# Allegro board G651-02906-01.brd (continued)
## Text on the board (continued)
User.45: FIGURE | SIZE | 0.8 | 0.1 | 0.15 | 0.2 | DRILL CHART: TOP to BOTTOM | ALL UNITS ARE IN MILLIMETERS | DRILL CHART: TOP to L2 | DRILL CHART: L3 to BOTTOM | DRILL CHART: L2 to L3 | TOLERANCE | +0.05/-0.05 | +0.0/-0.0 | PLATED | NON-PLATED | QTY | 2 | 234 | 252 | 231 | TP15 | TP16 | R8 | DS1 | L4 | TP1 | TP3 | L3 | Y2 | C8 | TP4 | TP9 | TP2 | TP10 | TP8 | R2 | R1 | R5 | R6 | R3 | R4 | R20 | R18 | R13 | R7 | C16 | C1 | C2 | R9 | TP18 | TP17 | C10 | C9 | D1 | D2 | L1 | C7 | C19 | L2 | C18 | C17 | R11 | C15 | C13 | C22 | C20 | C23 | C21 | C24 | R19 | C12 | R12 | R17 | Q2 | Q1 | C6 | C5 | DS2 | PCB edge | FAB NOTES: UNLESS OTHERWISE SPECIFIED | 1. FABRICATION STANDARDS | A) FABRICATE BOARDS IN ACCORDANCE WITH IPC-A-600 AND IPC-6012, CLASS 2. FINISHED BOARDS MUST MEET QUALITY CONFORMANCE TESTING AND INSPECTION AS SPECIFIED. | B) THE CONTROLLING UNIT OF MEASURE FOR THIS DRAWING AND THE SUPPLIED DATA IS METRICS OF INTERNATIONAL SYSTEM OF UNITS. DIMENSIONS THAT ARE SHOWN IN INCHES | ARE FOR REFERENCE ONLY. | C) THIS BOARD HAS CONTROLLED IMPEDANCE REQUIREMENTS. SEE IMPEDANCE CHARTS ON THIS SHEET. UNLESS OTHERWISE SPECIFIED, IMPEDANCE TOLERANCE IS +/- 10%. | D) BOW AND TWIST SHALL NOT EXCEED 0.75% MEASURED IN ACCORDANCE WITH IPC-TM-650. | E) REFER FAB MCO DRAWING PDF (*XXX-XXXXX-XX_MCO.PDF) FOR DIMENSIONS AND TOLERANCE DETAILS. MCO DRAWING TAKES FIRST PRIORITY AND DIMENSIONS NOT SPECIFIED | IN THE DRAWING SHALL BE CONTROLLED BY GERBER/ODB DATA. | 2. MATERIAL: | Optional 2.1 GLASS EPOXY, NATURAL COLOR, LAMINATED POLYCLAD EM390 OR EQUIVALENT. Tg OF 170C MINIMUM, CTE</= 3% PER | IPC-4101/4106 LATEST REVISION, MATERIAL TO BE HALOGEN FREE, MATERIAL MUST MEET UL 796/V-0 FLAMMABILITY RATING. | THE FINAL THICKNESS MEASURED OVER PLATING TO BE xxx mm, +/- 10%. MEASURED FROM SOLDERMASK TO SOLDERMASK | B) COPPER FOIL SHALL BE IN ACCORDANCE WITH IPC-4562. | C) VENDOR SHALL PROVIDE INTENDED STACKUP FOR ENGINEERING APPROVAL PRIOR TO FABRICATION. THE STACK-UP INCLUDE THE CCL, PP TYPE, COPPER FOIL, SOLDER MASK | AND ITS TARGET FINISHED THICKNESS EACH. | 3. SURFACE FINISH: | ALL EXTERNAL METAL FINISH NOT COVERED BY SOLDERMASK SHALL BE PLATED 3-6um OF ELECTROLESS NICKEL AND 0.03-0.10um OF | IMMERSION GOLD (ENIG) COMPLIANT WITH IPC-4552 LATEST REVISION. | Selective SELECTIVE FINISH ENIG/OSP IS REQUIRED. PLEASE REFERENCE SELECTIVE_GOLD_TOP AND SELECTIVE_GOLD_BOTTOM ARTWORK FOR | LOCATIONS REQUIRED. SELECTIVE FINISH: ENIG | Selective WHENEVER ENIG PAD TO OSP PAD SPACING IS LESS THAN 0.30MM, ENIG SURFACE FINISH SHALL TAKE PRIORITY. WRITTEN APPROVAL PRIOR TO FAB. | 4. BOARD FABRICATOR SHALL APPLY DATE CODE, FABRICATOR'S CAGE CODE, I.D. AND UL MARKING TO TOP SIDE OR BOTTOM SIDE WHERE APPLICABLE. | MARKING TO BE PERMANENT. LOCATION IS DEFINED ON SOLDERMASK XXX LAYER. | Optional MARKING TO BE COPPER PATTERN ETCH, SOLDER MASK OPENING, LASER ETCH ON GROUND. | MARKING TO BE LEGEND ON SOLDER MASK FOR ALLOWABLE AREA | 5. SOLDERMASK: | A) CONSTRUCTION TO BE SOLDER MASK OVER BARE COPPER (SMOBC), USING LIQUID PHOTOIMAGEABLE (LPI) SOLDER MASK MATERIAL, | TO BE APPLIED TO BOTH EXTERNAL LAYERS IN ACCORDANCE WITH IPC-SM-840, (TYPE T, CLASS 2). USE APPROPRIATE SOLDER MASK ARTWORK | FOR EACH SIDE OF THE BOARD. PUNCTURING OF TENTED HOLES IS NOT PERMISSIBLE. | B) SOLDER MASK MISREGISTRATION SHALL NOT EXCEED +/-37.5um PER TRUE POSITION. SOLDER MASK OVERLAP PERMITTED ON COPPER | DEFINED LANDS, BUT SHALL NOT EXCEED 25um. | SOLDER MASK OVERLAP PERMITTED ON COPPER DEFINED LANDS, BUT SHALL NOT EXCEED 25um. | C) SOLDER MASK MATERIAL TO BE XXX COLOR. GLOSSINESS SHALL NOT EXCEED 60. | D) SOLDER MASK OPENINGS ARE FINAL AND ARE NOT TO BE MODIFIED BY FABRICATOR. SOLDER MASK MAY EXIST ON PADS PER DESIGN. | CHANGES ARE ALLOWED WITH GOOGLE'S APPROVAL. | "SOME SMT PACKAGE FOOTPRINTS CONTAIN BOTH SOLDER MASK DEFINED(SMD) PADSAND COPPER DEFINED(NSMD) PADS. SOLDER MASK DEFINED | PADS SHALL BE MODIFIED TO CLOSELY MATCH COPPER DEFINED PADS WITHIN THE SAME SMT PACKAGE FOOTPRINT." | 6. DRILL BOARDS USING DRILL DATA, DRILL PATTERN. HOLE LOCATIONS MAY VARY WITHIN 0.076mm (RADIAL ERROR) MAX ABOUT TRUE POSITION. | DRILL For conventional only | 7. ALL MECHANICAL | 7. ALL MECHANICAL DRILL HOLES ARE PLATED-THROUGH UNLESS NOTED OTHERWISE. MINIMUM COPPER PLATING IN PLATED HOLES TO BE 17um. | COPPER PLATING IN TENTED HOLES SHALL NOT PLUG HOLES CLOSED. | Primary for ELIC7. ALL MECHANICAL DRILL HOLES ARE PLATED-THROUGH UNLESS NOTED OTHERWISE. MINIMUM COPPER PLATING IN PLATED | HOLES TO BE 10um. COPPER PLATING IN TENTED HOLES SHALL NOT PLUG HOLES CLOSED. | 8. DIAMETERS IN THE DRILL TABLE ARE FINISHED HOLE SIZE WITH +/-0.075 mm TOLERANCE | UNLESS OTHERWISE SPECIFIED IN THE DRILL TABLE. | 9. A CERTIFICATE OF COMPLIANCE WITH IPC-6012, CLASS 2, SHALL BE SUBMITTED WITH EACH BUILD AND CUSTOMER ORDER. | 10. VIAS(MECHANIC AND LASER) | Laser viaA) LASER VIAS BLIND AND BURIED ARE TO BE COPPER FILLED AND PLATED FLUSH. THE MAXIMIMUM MICRO-VIA FILL RECESSION (DIMPLE) | FOR OUTER LAYER SHALL NOT EXCEED 25 MICRONS OR 20% OF THE VIA DIAMETER, WHICHEVER IS GREATER. BURIED ONES SHOULD BE LESS THAN 10um. | C) ALL MECHANICAL VIAS TO BE NON-CONDUCTIVE EPOXY FILLED AND PLATED FLUSH(VIA IN PAD PLATED OVER) | 11. ALL UNUSED VIA PADS ON INTERNAL LAYERS TO BE REMOVED WITH GOOGLES APPROVAL | 12. FINISHED CONDUCTOR FEATURES: | A) LINE WIDTHS SHALL NOT VARY MORE THAN THE SMALLER OF 0.025MM OR 20% FROM THE CAD DATA. IMPEDANCE TRACE WIDTH TOLERANCE | IN PRIORITY OF THE FUNCTIONALITY COMPLIANCE WITH WRITTEN DFM APPROVAL. | OptionalB) PAD SIZE EQUAL TO OR LESS THAN 0.25MM SHALL NOT VARY MORE THAN +/- 0.025MM FROM THE CAD DATA. | 13. DIMENSIONS ARE AFTER ETCHING AND PLATING, AND ARE BASIC UNLESS OTHERWISE INDICATED. | 14. BOW AND TWIST SHALL NOT EXCEED 0.0075mm PER 1mm. | 15. ALL ARTWORK OR ODB++ DATA MAY BE ADJUSTED BY THE PCB FABRICATOR TO COMPENSATE FOR MANUFACTURING PROCESS TOLERANCES. | ADDITION OF FILLETS AT LINE/PAD INTERFACE IS PREFERRED. WRITTEN APPROVAL IS NEEDED PRIOR TO FAB. | 16. NO COPPER IS ALLOWED IN ROUTING TABS ON PANEL. | 17. TEST COUPON: PLACE FABRICATOR'S CAGE CODE, DATE CODE OR SERIAL NO. USING WHITE EPOXY INK OR COPPER ETCH. ONE METALLOGRAPHIC | SPECIMEN SHALL BE TESTED AND SUPPLIED WITH TEST EACH LOT OF BOARDS. A REPORT OF MEASUREMENTS, SHOWING AVERAGE PLATING THICKNESS AND QUALITY, | SHALL BE SUPPLIED WITH EACH SPECIMEN. TESTING SHALL INCLUDE THERMAL STRESS AND MICROSECTIONING PER IPC-TM-650, METHODS 2.1.1 AND 2.6.8. EACH | SPECIMEN SHALL BE IDENTIFIED AND TRACEABLE BACK TO THE ORIGINATING LOT. | 18. BARE BOARD ELECTRICAL TEST: BARE BOARDS SHALL BE ELECTRICALLY TESTED USING CAD GENERATED NETLIST DATA. THIS INFORMATION | TO BE SUPPLIED IN IPC-D-356 OR ODB++ FORMAT. TESTING SHALL FOLLOW THE GUIDELINES ESTABLISHED BY IPC-9252 CLASS II GUIDELINES AND REQUIREMENTS | FOR ELECTRICAL TESTING OF UNPOPULATED PRINTED BOARDS. COMPLETED ELECTRICAL TEST BOARDS MUST BE MARKED IN PERMANENT NON-CONDUCTIVE INK OR OTHER | APPROVED FORM NEXT TO SUPPLIER UL RECOGNITION MARK. | 19. ACCEPTANCE CRITERIA: | "COPPER SLIVERS THAT ARE LESS THAN 0.076 MM IN WIDTH BETWEEN ANTI-PAD TO PLANE EDGE, ANTI-PAD TO SPLIT PLANE AND ANTI-PAD TO ANTI-PAD MUST BE | REMOVED FROM THE MANUFACTURING ARTWORK. A NETLIST COMPARISON MUST BE PASSED WITH NO VIOLATION AFTER THE REMOVAL OF SLIVERS. ANY REQUIREMENT FOR | SLIVER REMOVAL ABOVE OR EQUAL TO THE 0.076 MM COPPER WIDTH MUST BE ADDRESSED AND APPROVED IN WRITING BY SUPPLIER." | THIS DESIGN HAVE NETS SHORTED INTENTIONALLY AND LIST IS PROVIDED BELOW. NETS NOT LISTED BELOW SHOULD BE QUESTIONED AND CLARIFIED IN DFM REVIEW. | 20. All HOMOGENOUS MATERIALS MUST COMPLY WITH THE GOOGLE RESTRICTED SUBSTANCES SPECIFICATION, 990-00012-00 LATEST REVISION, | WHICH INCLUDES: EU RoHS DIRECTIVE 2011/65/EC | REACH RESTRICTED SUBSTANCES | HALOGEN-FREE, <900 ppm Br, <900 ppm Cl, <1500 ppm Br + Cl COMBINED | BERYLLIUM-FREE, <1000 ppm | 21. IMPEDANCE: | A) PLEASE SEE CONTROLLED IMPEDANCE TABLE. | B) UNLESS OTHERWISE SPECIFIED IMPEDANCE TOLERANCE SHALL BE +/- 10% | C) FAB VENDOR CAN MICRO MODIFY TRACE WIDTH AND SPACING IN ORDER TO MEET IMPEDANCE. | D) IMPEDANCE REQUIREMENTS DEFINED IN TABLE, BUT NOT FOUND IN GERBER CAN BE IGNORED. | 22. SILK SCREEN: | A) SILK SCREEN CAN BE PRINTED ON BOTH SIDES OF THE BOARD WITH ROHS COMPLAINT NON CONDUCTIVE EPOXY INK. WHITE OR THE PANTONE COLOR CODING. | B) NO SILK SCREEN ALLLOWED ON EXPOSED CONDUCTIVE PATTERN. | C) SILKSCREEN MARKING FOR REGISTRATION PURPOSE OF IC OR BGA COULD BE NON SOLID POLARITY MARK AND NON CONTINUOUS LINE AROUND THE CONTOUR TO MINIMIZE THE BUMP. | NOTES: UNLESS OTHERWISE SPECIFIED- | 1.  INTERPRET DRAWING PER ASME Y14.100 | 2.  WORKMANSHIP SHALL BE EQUAL TO AND COMPLIANT WITH THE REQUIREMENTS OF IPC-A-610. LATEST RIVISION. | 3.  STAMP OR LABEL ASSEMBLY PN: 650-XXXXX-XX AND SERIAL NUMBER WITH CONTRASTING | COLOR INK IN THE LOCATION INDICATED. BARCODE SHALL BE PLACED IN LOCATION SPECIFIED. | 4.  ESD SHIELDING BAGS SHALL BE PLACED IN OVER-PACK CONTAINERS THAT PROVIDE | ADEQUATE PROTECTION FOR SAFE TRANSPORTATION AND STORAGE. OVER-PACK | CONTAINERS TO BE IDENTIFIED WITH ESD WARNING LABELS. | 5.  DESIGNATION ARE FOR REFERENCE ONLY AND DO NOT APPEAR ON INDIVIDUAL PARTS. | 6.  USE NO-CLEAN PROCESS. AQUEOUS CLEANING IS PROHIBITED. | 7.  MARK THE BILL OF MATERIALS REVISION IN THE AREA SHOWN. BAG AND TAG ACCEPTABLE | FOR ASSEMBLIES THAT ARE TOO SMALL OR TOO DENSE FOR STANDARD LABELING. | 8.  THIS ASSEMBLY DRAWING MAY SHOW COMPONENT LOCATIONS THAT ARE NO-STUFF OPTIONS. | REFER TO THE SPECIFIC BILL OF MATERIALS (BOM) FOR COMPONENTS USED IN EACH BOARD OPTION. | 9.  PRINTED CIRCUIT BOARD ASSEBMLY PROCESS AND MATERIALS USED MUST BE COMPLIANT WITH THE | RESTRICTION ON USE OF HAZARDOUS SUBSTANCES (R) DIRECTIVE. | SF_ENIG_TOP | SF_GOLD_HARD_BOT | SF_GOLD_HARD_TOP | SILKSCREEN_BOT | SILKSCREEN_TOP | LATCH AREA | J1 | U1 | R10 | U3 | U2 | J3 | Y1 | J2 | SW1 | A1
